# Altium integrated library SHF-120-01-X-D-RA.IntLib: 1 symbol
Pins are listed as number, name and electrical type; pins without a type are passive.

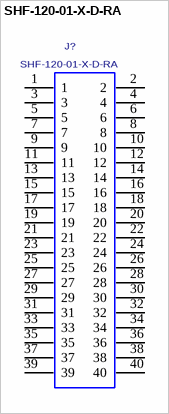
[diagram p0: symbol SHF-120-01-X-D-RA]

## SHF-120-01-X-D-RA
designator J?
0.05"X0.05" SHROUDED TERMINAL STRIP, 40 PINS.; MANUFACTURER: SAMTEC
footprint SHF-120-01-X-D-RA
pins: 1, 2, 3, 4, 5, 6, 7, 8, 9, 10, 11, 12, 13, 14, 15, 16, 17, 18, 19, 20, 21, 22, 23, 24, 25, 26, 27, 28, 29, 30, 31, 32, 33, 34, 35, 36, 37, 38, 39, 40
